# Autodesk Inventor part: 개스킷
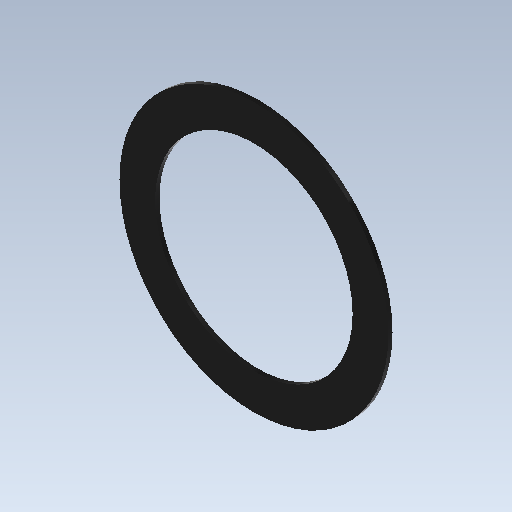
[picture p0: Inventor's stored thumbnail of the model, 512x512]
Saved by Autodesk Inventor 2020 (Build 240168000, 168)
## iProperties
Created: 2022-05
Part Number: 개스킷
Material: 황동, 연질 노란색
Document SubType Name: Modeling
Designer: mdu-01
Density: 1 g/cm^3
Appearance: 매끄러움 - 검은색
Author: mdu-01
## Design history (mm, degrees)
sketch "스케치1"
  geometry: C1 r 23.5 at (0, 0); C2 r 32 at (0, 0); 1 further point
  constraints: 2 centre point, 2 coincident
  dimensions: "d0" = 47 diameter of C1; "d1" = 64 diameter of C2
extrude "돌출1" new body sketch "스케치1" stored distance "d2" = 1; taper "d3" = 0 deg
node "솔리드1"
